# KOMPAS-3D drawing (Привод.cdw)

Referenced files: Редуктор 3_1.cdw
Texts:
  Привод
  Виталик
  Текст на чертеже
  Размерные надписи
  Шероховатость
  Линия выноски #1
  Линия выноски #2
  Линия выноски #3
  Отклонения формы и база
  Заголовок таблицы
  Ячейка таблицы
  Стрелка вида
  Обозначение изменения
  Фигурная скобка
  Номер узла
  Марка координационной оси
  VRCB
  Выносная надпись
  Обозначение узла
  Марка/позиционное обозначение с линией-выноской
  Марка/позиционное обозначение на линии
  Марка/позиционное обозначение без линии-выноски
  K5LT17
  K5LT27
  K5LT327687
  K5LT37
  K5LT15
  Стили документа
Dimensions and other numbers on the sheet: 7; 1120; 100; 504; 216; 1; 2; 4; 5; 6; 8; 13; 15; 3; 14; 510; 178; 260; 64; 130; 1:2,5; 0; 9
